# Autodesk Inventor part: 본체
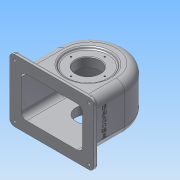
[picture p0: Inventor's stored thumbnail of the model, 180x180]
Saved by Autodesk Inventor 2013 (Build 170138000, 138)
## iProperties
Created: 2016-01
Part Number: 본체
Material: 알루미늄 6061
Document SubType Name: Modeling
Designer: Administrator
Density: 2.71 g/cm^3
Mass: 808.529 g
Surface Area: 1002.12 cm^2
Volume: 298.35 cm^3
Author: Administrator
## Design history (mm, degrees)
sketch "스케치1"
  geometry: L1 (57, -57)-(-57, -57); L2 (-57, -57)-(-57, 0); L3 (57, 0)-(57, -57); A1 r 57 centre (0, 0) between (57, 0) and (-57, 0); 2 further points
  constraints: 6 end point, 2 point on circle, 1 centre point, 1 coincident, 1 midpoint, 1 parallel, 1 perpendicular, 1 tangent, 1 vertical alignment
  dimensions: "d0" = 57 radius of A1; "d2" = 57 distance from line of point (0, 0) L1; "d3" = 114 distance between parallel lines of L3 L2
extrude "돌출1" new body sketch "스케치1" stored distance "d4" = 77; taper "d5" = 0 deg
sketch "스케치2"
  geometry: L1 (-13, -90.5)-(127, -90.5); L2 (127, -90.5)-(127, 13.5); L3 (127, 13.5)-(-13, 13.5); L4 (-13, 13.5)-(-13, -90.5); L5 (-13, -90.5)-(127, 13.5); L6 (127, -90.5)-(-13, 13.5); 1 further point
  constraints: 12 end point, 2 midpoint, 2 parallel, 1 horizontal, 1 perpendicular
  dimensions: "d6" = 140 distance of L3.end L2.end; "d7" = 104 distance of L2.end L1.end
extrude "돌출2" join sketch "스케치2" distance "d8" = 7; taper "d9" = 0 deg
sketch "스케치3"
  geometry: L1 (57, 0)-(57, -57) reference; L2 (-57, -57)-(-57, 0) reference; L3 (-70, -64)-(70, -64) reference; L4 (-57, -57)-(-57, -64); L5 (57, -57)-(57, -64); L6 (-51, -64)-(-51, -57); L7 (-51, -57)-(-51, 0); L8 (51, 0)-(51, -57); L9 (51, -57)-(51, -64); L10 (51, -64)-(-51, -64); A1 r 57 centre (0, 0) between (57, 0) and (-57, 0) reference; A2 r 51 centre (0, 0) between (51, 0) and (-51, 0); 1 further point
  constraints: 14 end point, 2 collinear, 2 perpendicular, 2 point on circle, 2 point on line, 1 centre point, 4 other
  dimensions: "d10" = 6 radial gap between concentric circles of A1 A2
extrude "돌출3" cut sketch "스케치3" stored distance "d11" = 67; taper "d12" = 0 deg
fillet "모깎기1" dims "d13" = 14
fillet "모깎기2" dims "d14" = 9
sketch "스케치4"
  geometry: L1 (35.747, 33.5)-(24, 19.5); L2 (24, 19.5)-(-4, 19.5); L3 (33.416, 38.5)-(30.899, 35.5); L4 (-64, 52)-(-64, -52) reference; L5 (-4, 0)-(-4, 38.5); L6 (42, 33.5)-(0, 33.5) reference; L7 (35.747, 33.5)-(-4, 33.5); L8 (33.416, 38.5)-(-4, 38.5); L9 (30.899, 35.5)-(-4, 35.5); L10 (0, 38.5)-(43, 38.5) reference; 1 further point
  constraints: 14 end point, 3 perpendicular, 3 point on line, 2 collinear, 2 parallel
  dimensions: "d17" = 50 deg angle of L2 L1; "d19" = 5 distance between parallel lines of L3 L1; "d37" = 60 distance between parallel lines of L5 L4; "d38" = 16 distance between parallel lines of L9 L2; "d39" = 3 distance between parallel lines of L9 L8; "d40" = 56 diameter of L1.end L5
revolve "회전3" stored, may be unused: angle "d41" = 90 deg
revolve "회전4" stored, may be unused: angle "d42" = 90 deg
sketch "스케치8"
  geometry: C1 r 34.899 at (0, 0) reference; C2 r 20 at (0, 0); 1 further point
  constraints: 1 centre point, 1 coincident
  dimensions: "d43" = 40 diameter of C2
extrude "돌출7" cut sketch "스케치8" stored distance "d44" = 10; taper "d45" = 0 deg
sketch "스케치9"
  geometry: C1 r 20 at (0, -4) reference; C2 r 31 at (0, -4)
  constraints: 1 centre point, 1 coincident
  dimensions: "d46" = 62 diameter of C2
extrude "돌출8" join sketch "스케치9" distance "d47" = 10; taper "d48" = 0 deg
sketch "스케치10"
  geometry: C1 r 31 at (0, 0) reference; C2 r 20 at (0, 0); 1 further point
  constraints: 1 centre point, 1 coincident
  dimensions: "d49" = 40 diameter of C2
extrude "돌출9" cut sketch "스케치10" stored distance "d50" = 10; taper "d51" = 0 deg
node "작업 평면1"
sketch "스케치11"
  geometry: C1 r 6 at (0, 0); 1 further point
  constraints: 1 centre point, 1 coincident
  dimensions: "d53" = 12 diameter of C1
extrude "돌출10" join sketch "스케치11" stored distance "d54" = 10; taper "d55" = 0 deg
fillet "모깎기4" dims "d56" = 8
sketch "스케치12"
  geometry: C1 r 2.5 at (-5, 82.5); C2 r 2.5 at (-5, -5.5); C3 r 2.5 at (119, -5.5); C4 r 2.5 at (119, 82.5); A1 r 8 centre (-5, -5.5) between (-13, -5.5) and (-5, -13.5) reference; A2 r 8 centre (119, -5.5) between (119, -13.5) and (127, -5.5) reference; A3 r 8 centre (119, 82.5) between (127, 82.5) and (119, 90.5) reference; A4 r 8 centre (-5, 82.5) between (-5, 90.5) and (-13, 82.5) reference; 1 further point
  constraints: 4 centre point, 4 coincident
  dimensions: "d57" = 5 diameter of C1; "d58" = 5 diameter of C2; "d59" = 5 diameter of C3; "d60" = 5 diameter of C4
extrude "돌출11" cut sketch "스케치12" stored distance "d61" = 10; taper "d62" = 0 deg
fillet "모깎기5" dims "d63" = 1
chamfer "모따기2" distance "d64" = 1; stored, may be unused: second distance "d65" = 2, angle "d66" = 45 deg
fillet "모깎기6" dims "d67" = 3
sketch "스케치13"
  geometry: C1 r 21 at (0, 0) reference; 2 further points
  constraints: 1 vertical alignment
  dimensions: "d68" = 28 distance of C1.centre point (0, 28)
hole "구멍1" sketch "스케치13" at (0, 28) diameter "d69" = 2.459; stored, may be unused: countersink angle "d73" = 90 deg, drill point angle "d75" = 118 deg; dims "d70" = 7, "d71" = 4, "d72" = 2, "d74" = 9
sketch "스케치14"
  geometry: C1 r 31 at (0, 0) reference; 2 further points
  constraints: 1 vertical alignment
  dimensions: "d79" = 24 distance of C1.centre point (0, 24)
hole "구멍2" sketch "스케치14" at (0, 24) diameter "d80" = 2.459; stored, may be unused: countersink angle "d84" = 90 deg, drill point angle "d86" = 118 deg; dims "d81" = 6, "d82" = 4, "d83" = 2, "d85" = 8
hole "구멍3" diameter "d92" = 4.459; stored, may be unused: countersink angle "d96" = 90 deg, drill point angle "d98" = 118 deg; dims "d90" = 10, "d91" = 10, "d93" = 6, "d94" = 4, "d95" = 2, "d97" = 8
sketch "스케치15"
  geometry: L1 (-14, 0)-(-14, -56) reference; L2 (-19.5, -64)-(-27.5, -64) reference; 2 further points
  constraints: 1 other
  dimensions: "d99" = 38.5 distance from line of L1 point (24.5, -34); "d100" = 30 distance from line of L2 point (24.5, -34)
feature "엠보싱1" sketch "스케치15" dims "d0" = 57, "d2" = 57, "d3" = 114, "d101" = 0.5, "d102" = 0
fillet "모깎기8" dims "d104" = 3
fillet "모깎기9" dims "d105" = 3
node "솔리드1"
pattern_circular "원형 패턴1" dims angle "d77" = 360 deg
pattern_circular "원형 패턴2" dims angle "d88" = 360 deg
other parameters: "d52" = 63
